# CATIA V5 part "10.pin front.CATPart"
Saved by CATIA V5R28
Part number: Pin front
Bounding box of the stored display mesh (mm): x -54 to 54, y -5 to 5, z -5 to 5
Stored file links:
  D:\Catia Cycle design\10.pin front.CATPart
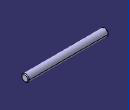
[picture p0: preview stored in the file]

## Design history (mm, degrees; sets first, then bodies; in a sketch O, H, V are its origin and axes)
Set1
  Sketch1 on yz-plane, origin (0, 0, 0), H (0, 1, 0), V (0, 0, 1)
    circle A1 centre (0, 0) radius 5
    radius A1 = 5
Body1 (main body)
  Pad1: profile Sketch1, direction (1, 0, 0), length 54, mirrored extent
  Chamfer1: length 1, angle 45, on edge [face of Pad1 from Sketch1.A1 | end face of Pad1]; edge [start face of Pad1 | face of Pad1 from Sketch1.A1]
